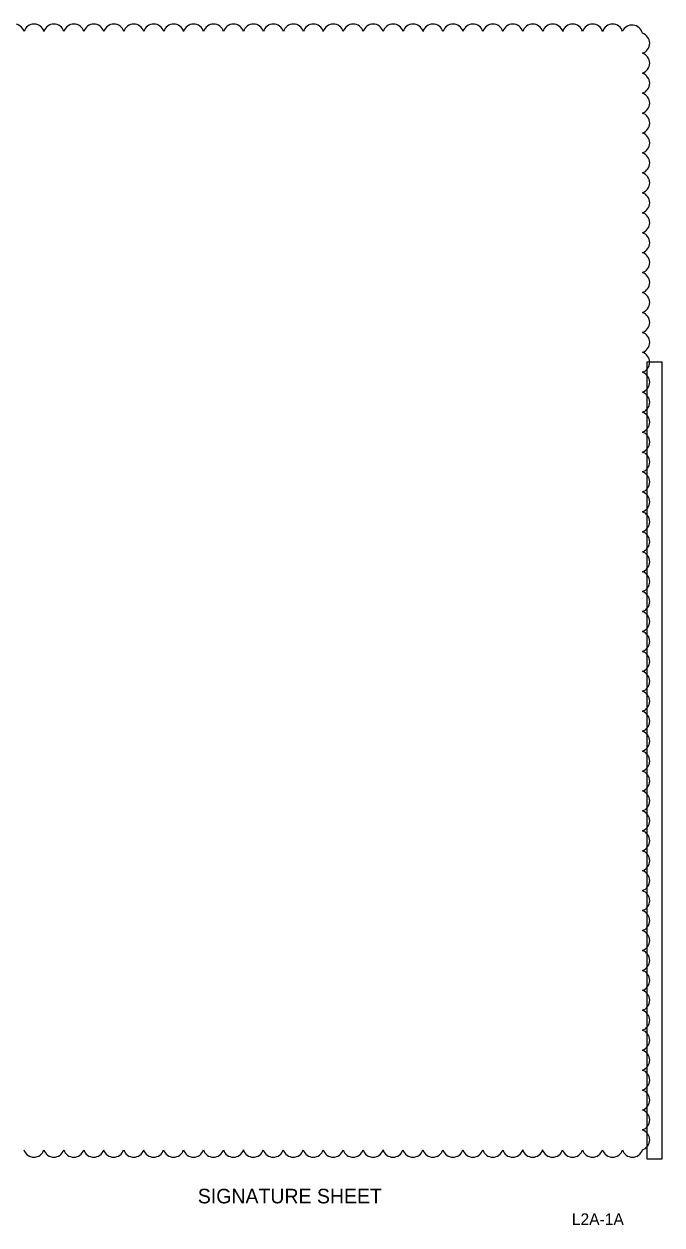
# Model space of a CAD drawing. Extents: x -811 to -790, y -2284 to -2178.
# Drawn here: x -800.69 to -795.22, y -2199.25 to -2188.94 of the extents above; entities that cross this region are included whole.
import ezdxf

# ---------------------------------------------------------------- set-up
doc = ezdxf.new("R2010")
doc.units = 0
for name, color, linetype in [('AdhocPoint_dp', 7, 'Continuous'), ('PlotBorder_dp', 7, 'Continuous'), ('SheetLines_dp', 7, 'Continuous'), ('TextTitle', 7, 'Continuous')]:
    doc.layers.add(name, color=color, linetype=linetype)

msp = doc.modelspace()

# ---------------------------------------------------------------- linework, layer by layer
at = {"layer": 'AdhocPoint_dp'}
msp.add_lwpolyline([(-795.346, -2191.838), (-795.218, -2191.838), (-795.218, -2198.68), (-795.346, -2198.68)], close=True, dxfattribs=at)
at = {"layer": 'TextTitle'}
for centre, radius, start, end in [((-800.775, -2189.028), 0.0897, 17.5, 162.5), ((-800.604, -2189.028), 0.0897, 17.5, 162.5), ((-800.433, -2189.028), 0.0897, 17.5, 162.5), ((-800.262, -2189.028), 0.0897, 17.5, 162.5), ((-800.091, -2189.028), 0.0897, 17.5, 162.5), ((-799.919, -2189.028), 0.0897, 17.5, 162.5), ((-799.748, -2189.028), 0.0897, 17.5, 162.5), ((-799.577, -2189.028), 0.0897, 17.5, 162.5), ((-799.406, -2189.028), 0.0897, 17.5, 162.5), ((-799.235, -2189.028), 0.0897, 17.5, 162.5), ((-799.064, -2189.028), 0.0897, 17.5, 162.5), ((-798.893, -2189.028), 0.0897, 17.5, 162.5), ((-798.722, -2189.028), 0.0897, 17.5, 162.5), ((-798.551, -2189.028), 0.0897, 17.5, 162.5), ((-798.379, -2189.028), 0.0897, 17.5, 162.5), ((-798.208, -2189.028), 0.0897, 17.5, 162.5), ((-798.037, -2189.028), 0.0897, 17.5, 162.5), ((-797.866, -2189.028), 0.0897, 17.5, 162.5), ((-797.695, -2189.028), 0.0897, 17.5, 162.5), ((-797.524, -2189.028), 0.0897, 17.5, 162.5), ((-797.353, -2189.028), 0.0897, 17.5, 162.5), ((-797.182, -2189.028), 0.0897, 17.5, 162.5), ((-797.01, -2189.028), 0.0897, 17.5, 162.5), ((-796.839, -2189.028), 0.0897, 17.5, 162.5), ((-796.668, -2189.028), 0.0897, 17.5, 162.5), ((-796.497, -2189.028), 0.0897, 17.5, 162.5), ((-796.326, -2189.028), 0.0897, 17.5, 162.5), ((-796.155, -2189.028), 0.0897, 17.5, 162.5), ((-795.984, -2189.028), 0.0897, 17.5, 162.5), ((-795.813, -2189.028), 0.0897, 17.5, 162.5), ((-795.641, -2189.028), 0.0897, 17.5, 162.5), ((-795.474, -2189.036), 0.0896, 11.7454, 156.7454), ((-795.413, -2189.103), 0.0897, 287.5, 72.5), ((-795.413, -2189.274), 0.0897, 287.5, 72.5), ((-795.413, -2189.446), 0.0897, 287.5, 72.5), ((-795.413, -2189.617), 0.0897, 287.5, 72.5), ((-795.413, -2189.788), 0.0897, 287.5, 72.5), ((-795.413, -2189.959), 0.0897, 287.5, 72.5), ((-795.413, -2190.13), 0.0897, 287.5, 72.5), ((-795.413, -2190.301), 0.0897, 287.5, 72.5), ((-795.413, -2190.472), 0.0897, 287.5, 72.5), ((-795.413, -2190.643), 0.0897, 287.5, 72.5), ((-795.413, -2190.815), 0.0897, 287.5, 72.5), ((-795.413, -2190.986), 0.0897, 287.5, 72.5), ((-795.413, -2191.157), 0.0897, 287.5, 72.5), ((-795.413, -2191.328), 0.0897, 287.5, 72.5), ((-795.413, -2191.499), 0.0897, 287.5, 72.5), ((-795.413, -2191.67), 0.0897, 287.5, 72.5), ((-795.413, -2191.841), 0.0897, 287.5, 72.5), ((-795.413, -2192.012), 0.0897, 287.5, 72.5), ((-795.413, -2192.184), 0.0897, 287.5, 72.5), ((-795.413, -2192.355), 0.0897, 287.5, 72.5), ((-795.413, -2192.526), 0.0897, 287.5, 72.5), ((-795.413, -2192.697), 0.0897, 287.5, 72.5), ((-795.413, -2192.868), 0.0897, 287.5, 72.5), ((-795.413, -2193.039), 0.0897, 287.5, 72.5), ((-795.413, -2193.21), 0.0897, 287.5, 72.5), ((-795.413, -2193.381), 0.0897, 287.5, 72.5), ((-795.413, -2193.553), 0.0897, 287.5, 72.5), ((-795.413, -2193.724), 0.0897, 287.5, 72.5), ((-795.413, -2193.895), 0.0897, 287.5, 72.5), ((-795.413, -2194.066), 0.0897, 287.5, 72.5), ((-795.413, -2194.237), 0.0897, 287.5, 72.5), ((-795.413, -2194.408), 0.0897, 287.5, 72.5), ((-795.413, -2194.579), 0.0897, 287.5, 72.5), ((-795.413, -2194.75), 0.0897, 287.5, 72.5), ((-795.413, -2194.922), 0.0897, 287.5, 72.5), ((-795.413, -2195.093), 0.0897, 287.5, 72.5), ((-795.413, -2195.264), 0.0897, 287.5, 72.5), ((-795.413, -2195.435), 0.0897, 287.5, 72.5), ((-795.413, -2195.606), 0.0897, 287.5, 72.5), ((-795.413, -2195.777), 0.0897, 287.5, 72.5), ((-795.413, -2195.948), 0.0897, 287.5, 72.5), ((-795.413, -2196.119), 0.0897, 287.5, 72.5), ((-795.413, -2196.29), 0.0897, 287.5, 72.5), ((-795.413, -2196.462), 0.0897, 287.5, 72.5), ((-795.413, -2196.633), 0.0897, 287.5, 72.5), ((-795.413, -2196.804), 0.0897, 287.5, 72.5), ((-795.413, -2196.975), 0.0897, 287.5, 72.5), ((-795.413, -2197.146), 0.0897, 287.5, 72.5), ((-795.413, -2197.317), 0.0897, 287.5, 72.5), ((-795.413, -2197.488), 0.0897, 287.5, 72.5), ((-795.413, -2197.659), 0.0897, 287.5, 72.5), ((-795.413, -2197.831), 0.0897, 287.5, 72.5), ((-795.413, -2198.002), 0.0897, 287.5, 72.5), ((-795.413, -2198.173), 0.0897, 287.5, 72.5), ((-795.413, -2198.344), 0.0897, 287.5, 72.5), ((-795.413, -2198.515), 0.0897, 287.5, 72.5), ((-800.605, -2198.574), 0.0897, 197.5, 342.5), ((-800.434, -2198.574), 0.0897, 197.5, 342.5), ((-800.263, -2198.574), 0.0897, 197.5, 342.5), ((-800.092, -2198.574), 0.0897, 197.5, 342.5), ((-799.921, -2198.574), 0.0897, 197.5, 342.5), ((-799.749, -2198.574), 0.0897, 197.5, 342.5), ((-799.578, -2198.574), 0.0897, 197.5, 342.5), ((-799.407, -2198.574), 0.0897, 197.5, 342.5), ((-799.236, -2198.574), 0.0897, 197.5, 342.5), ((-799.065, -2198.574), 0.0897, 197.5, 342.5), ((-798.894, -2198.574), 0.0897, 197.5, 342.5), ((-798.723, -2198.574), 0.0897, 197.5, 342.5), ((-798.552, -2198.574), 0.0897, 197.5, 342.5), ((-798.38, -2198.574), 0.0897, 197.5, 342.5), ((-798.209, -2198.574), 0.0897, 197.5, 342.5), ((-798.038, -2198.574), 0.0897, 197.5, 342.5), ((-797.867, -2198.574), 0.0897, 197.5, 342.5), ((-797.696, -2198.574), 0.0897, 197.5, 342.5), ((-797.525, -2198.574), 0.0897, 197.5, 342.5), ((-797.354, -2198.574), 0.0897, 197.5, 342.5), ((-797.183, -2198.574), 0.0897, 197.5, 342.5), ((-797.011, -2198.574), 0.0897, 197.5, 342.5), ((-796.84, -2198.574), 0.0897, 197.5, 342.5), ((-796.669, -2198.574), 0.0897, 197.5, 342.5), ((-796.498, -2198.574), 0.0897, 197.5, 342.5), ((-796.327, -2198.574), 0.0897, 197.5, 342.5), ((-796.156, -2198.574), 0.0897, 197.5, 342.5), ((-795.985, -2198.574), 0.0897, 197.5, 342.5), ((-795.814, -2198.574), 0.0897, 197.5, 342.5), ((-795.642, -2198.574), 0.0897, 197.5, 342.5), ((-795.471, -2198.574), 0.0897, 197.5, 342.5)]:
    msp.add_arc(centre, radius, start, end, dxfattribs=at)

# ---------------------------------------------------------------- texts
at = {"layer": 'PlotBorder_dp'}
msp.add_text('       SIGNATURE SHEET         ', height=0.125, dxfattribs=at).set_placement((-799.524, -2199.06))
at = {"layer": 'SheetLines_dp'}
msp.add_text('L2A-1A', height=0.1, dxfattribs=at).set_placement((-795.991, -2199.246))

doc.saveas('drawing.dxf')
